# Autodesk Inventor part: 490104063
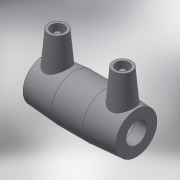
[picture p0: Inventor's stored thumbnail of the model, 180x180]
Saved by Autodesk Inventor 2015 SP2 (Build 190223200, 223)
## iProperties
Created: 2017-06
Part Number: 490104063
Material: Generic
Description: PLASSON COUPLER 63-63
Document SubType Name: Modeling
Designer: KIM
Mass: 55.0731 g
Surface Area: 148.067 cm^2
Volume: 55.0731 cm^3
Density: 1 g/cm^3
Appearance: Default
Author: KIM
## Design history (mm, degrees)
derived "490104.ipt"
feature "Solid1::490104.ipt"
tag "TaggingFeature1"
body "Solid1"
other parameters: "d0" = 117, "d1" = 63, "d2" = 82, "d3" = 57, "d4" = 39, "d5" = 73.8, "d6" = 59.85, "d7" = 63, "d8" = 168 deg, "d10" = 22.8, "d11" = 7.6, "d13" = 117, "d14" = 17.6296, "d15" = 57, "d16" = 57, "d17" = 59.85, "d18" = 63, "d19" = 3.52592, "d20" = 168 deg, "d22" = 77.08, "d23" = 82, "d24" = 74.7676, "d25" = 135 deg, "d26" = 46.8, "d27" = 135 deg, "d29" = 57, "d30" = 14, "d31" = 40.95, "d34" = 5 deg, "d35" = 15, "d39" = 5 deg, "d41" = 4, "d42" = 14, "d43" = 0, "d45" = 4, "d46" = 14, "d47" = 0, "d48" = 3, "d49" = 0, "d50" = 3, "d51" = 0, "d52" = 16.53, "d53" = 4.1325, "d_" = 63, "L_" = 117, "L_1" = 57, "D_" = 82, "A_" = 57, "d_2" = 12
